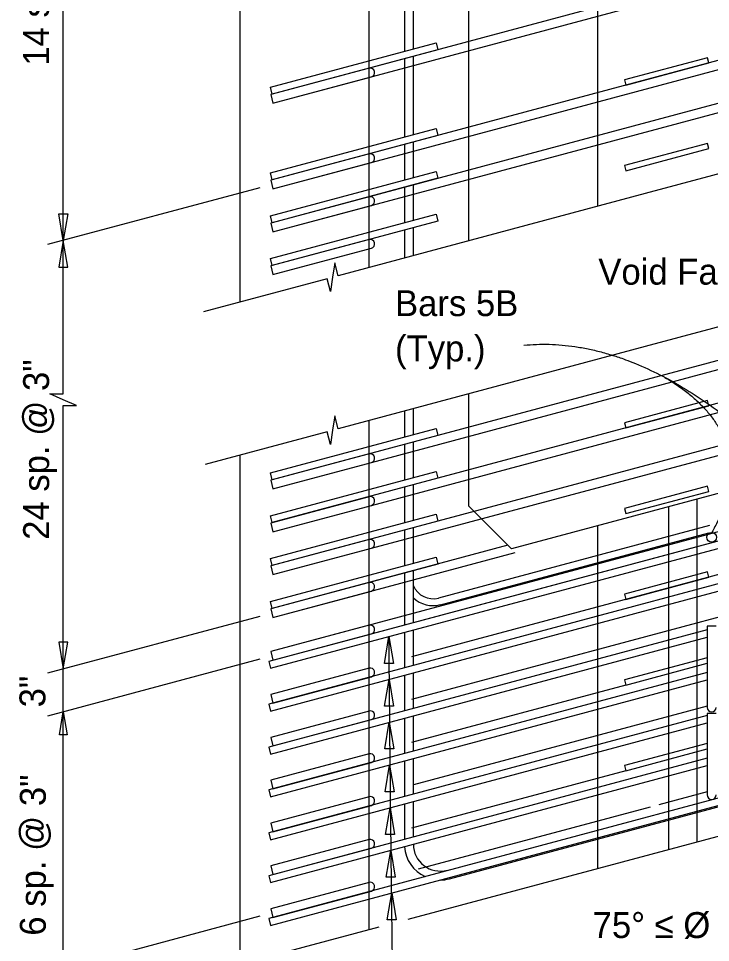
# Model space of a CAD drawing. Extents: x 120658.6 to 120712.1, y 120647.1 to 120669.9.
# Drawn here: x 120676.96 to 120681, y 120653.49 to 120658.88 of the extents above; entities that cross this region are included whole.
import ezdxf

# ---------------------------------------------------------------- set-up
doc = ezdxf.new("R2010")
doc.units = 0
for name, color, linetype in [('BeamConc', 7, 'Continuous'), ('BeamConc_h', 7, 'Continuous'), ('Dimension', 7, 'Continuous'), ('Miscellaneous', 7, 'Continuous'), ('Rebar', 7, 'Continuous'), ('Rebar_h', 7, 'Continuous'), ('TextStructures', 7, 'Continuous')]:
    doc.layers.add(name, color=color, linetype=linetype)

msp = doc.modelspace()

# ---------------------------------------------------------------- linework, layer by layer
at = {"layer": 'BeamConc'}
for p, q in [((120679.5908, 120657.5812), (120679.5908, 120659.5478)), ((120678.2575, 120657.224), (120678.2575, 120659.1906)), ((120684.1025, 120656.9257), (120679.8408, 120655.7838)), ((120679.5908, 120656.0338), (120679.5908, 120656.6888)), ((120678.2575, 120653.4221), (120678.2575, 120656.3316)), ((120679.8408, 120655.7838), (120679.5908, 120656.0338)), ((120687.0305, 120655.7103), (120679.2355, 120653.6216)), ((120679.0655, 120653.5761), (120678.3179, 120653.3758))]:
    msp.add_line(p, q, dxfattribs=at)
at = {"layer": 'BeamConc_h'}
for p, q in [((120680.3408, 120659.7487), (120680.3408, 120657.7821)), ((120679.0075, 120659.3915), (120679.0075, 120657.4249)), ((120679.0075, 120656.5326), (120679.0075, 120653.5605)), ((120680.3408, 120655.9178), (120680.3408, 120653.9178))]:
    msp.add_line(p, q, dxfattribs=at)
at = {"layer": 'Dimension'}
for p, q in [((120678.372, 120657.8903), (120677.1344, 120657.5586)), ((120678.372, 120655.3903), (120677.1344, 120655.0586)), ((120678.372, 120655.1403), (120677.1344, 120654.8086)), ((120678.372, 120653.6403), (120677.1344, 120653.3086))]:
    msp.add_line(p, q, dxfattribs=at)
for points in [[(120677.226, 120657.5832), (120677.226, 120659.3202), (120677.3035, 120659.3202), (120677.226, 120659.354), (120677.1485, 120659.3877), (120677.226, 120659.3877), (120677.226, 120666.7254)], [(120684.7814, 120658.9716), (120682.7067, 120658.4158), (120682.6867, 120658.4906), (120682.6742, 120658.4071), (120682.6615, 120658.3234), (120682.6415, 120658.3983), (120680.6202, 120657.8569)], [(120685.0801, 120658.1592), (120682.7067, 120657.5235), (120682.6867, 120657.5983), (120682.6742, 120657.5147), (120682.6615, 120657.4311), (120682.6415, 120657.506), (120680.6202, 120656.9646)], [(120680.6202, 120657.8569), (120678.8294, 120657.3772), (120678.8094, 120657.452), (120678.7969, 120657.3685), (120678.7842, 120657.2848), (120678.7642, 120657.3597), (120678.0441, 120657.1668)], [(120677.226, 120652.0096), (120677.226, 120656.6201), (120677.3035, 120656.6201), (120677.226, 120656.6539), (120677.1485, 120656.6876), (120677.226, 120656.6876), (120677.226, 120657.5832)], [(120680.6202, 120656.9646), (120678.8294, 120656.4849), (120678.8094, 120656.5597), (120678.7969, 120656.4761), (120678.7842, 120656.3925), (120678.7642, 120656.4674), (120678.0531, 120656.2769)]]:
    msp.add_lwpolyline(points, dxfattribs=at)
for points in [[(120677.226, 120657.5832), (120677.1996, 120657.7394), (120677.2525, 120657.7394)], [(120677.226, 120657.5832), (120677.1996, 120657.427), (120677.2525, 120657.427)], [(120679.1251, 120655.2719), (120679.1516, 120655.1157), (120679.0986, 120655.1157)], [(120677.226, 120655.0832), (120677.2525, 120655.2394), (120677.1996, 120655.2394)], [(120679.126, 120655.0222), (120679.1525, 120654.866), (120679.0996, 120654.866)], [(120677.2261, 120654.8331), (120677.2482, 120654.6993), (120677.204, 120654.6993)], [(120679.1273, 120654.7726), (120679.1538, 120654.6164), (120679.1008, 120654.6164)], [(120679.1293, 120654.523), (120679.1557, 120654.3668), (120679.1028, 120654.3668)], [(120679.132, 120654.2738), (120679.1584, 120654.1176), (120679.1055, 120654.1176)], [(120679.1358, 120654.0248), (120679.1623, 120653.8686), (120679.1094, 120653.8686)], [(120679.1419, 120653.7765), (120679.1683, 120653.6203), (120679.1154, 120653.6203)]]:
    msp.add_lwpolyline(points, close=True, dxfattribs=at)
for points in [[(120679.9122, 120656.9718), (120680.71, 120657.051), (120681.6484, 120656.0418)], [(120680.7352, 120656.7842), (120681.3153, 120656.4395), (120681.0094, 120655.88)], [(120679.5373, 120652.9108), (120679.2444, 120652.879), (120679.1509, 120653.1895), (120679.1427, 120653.5375), (120679.1252, 120655.2719)]]:
    msp.add_open_spline(points, degree=2, dxfattribs=at)
at = {"layer": 'Miscellaneous'}
for p, q in [((120680.922, 120656.0735), (120680.922, 120654.0735)), ((120680.7553, 120656.0289), (120680.7553, 120654.0289))]:
    msp.add_line(p, q, dxfattribs=at)
at = {"layer": 'Rebar'}
for p, q in [((120679.2158, 120659.1433), (120679.2158, 120658.6865)), ((120679.2679, 120658.7005), (120679.2679, 120659.1573)), ((120678.4342, 120658.4771), (120679.4002, 120658.7359)), ((120679.4109, 120658.6956), (120678.445, 120658.4368)), ((120679.4002, 120658.7359), (120679.4109, 120658.6956)), ((120679.2158, 120658.6433), (120679.2158, 120658.1865)), ((120679.2679, 120658.2005), (120679.2679, 120658.6573)), ((120679.0093, 120658.5879), (120678.4356, 120658.4342)), ((120678.449, 120658.3839), (120679.0228, 120658.5376)), ((120678.445, 120658.4368), (120678.4342, 120658.4771)), ((120678.4356, 120658.4342), (120678.449, 120658.3839)), ((120678.4342, 120657.9771), (120679.4002, 120658.2359)), ((120679.4002, 120658.2359), (120679.4109, 120658.1956)), ((120679.4109, 120658.1956), (120678.445, 120657.9368)), ((120679.2679, 120657.9505), (120679.2679, 120658.1573)), ((120679.2158, 120658.1433), (120679.2158, 120657.9365)), ((120679.0093, 120658.0879), (120678.4356, 120657.9342)), ((120678.449, 120657.8839), (120679.0228, 120658.0376)), ((120678.4342, 120657.7271), (120679.4002, 120657.9859)), ((120678.445, 120657.9368), (120678.4342, 120657.9771)), ((120679.4109, 120657.9456), (120678.445, 120657.6868)), ((120679.4002, 120657.9859), (120679.4109, 120657.9456)), ((120678.4356, 120657.9342), (120678.449, 120657.8839)), ((120679.2158, 120657.8933), (120679.2158, 120657.6865)), ((120679.2679, 120657.7005), (120679.2679, 120657.9073)), ((120679.0093, 120657.8379), (120678.4356, 120657.6842)), ((120678.449, 120657.6339), (120679.0228, 120657.7876)), ((120678.4342, 120657.4771), (120679.4002, 120657.7359)), ((120678.445, 120657.6868), (120678.4342, 120657.7271)), ((120679.4002, 120657.7359), (120679.4109, 120657.6956)), ((120678.4356, 120657.6842), (120678.449, 120657.6339)), ((120679.4109, 120657.6956), (120678.445, 120657.4368)), ((120679.2158, 120657.6433), (120679.2158, 120657.4807)), ((120679.2679, 120657.4947), (120679.2679, 120657.6573)), ((120679.0093, 120657.5879), (120678.4356, 120657.4342)), ((120678.449, 120657.3839), (120679.0228, 120657.5376)), ((120678.445, 120657.4368), (120678.4342, 120657.4771)), ((120678.4356, 120657.4342), (120678.449, 120657.3839)), ((120686.9134, 120657.1519), (120678.4242, 120654.8772)), ((120678.435, 120654.837), (120686.9242, 120657.1117)), ((120685.4351, 120657.0058), (120678.4242, 120655.1272)), ((120678.435, 120655.087), (120685.4459, 120656.9656)), ((120679.2679, 120656.4505), (120679.2679, 120656.6023)), ((120679.2158, 120656.5884), (120679.2158, 120656.4365)), ((120678.4342, 120656.2271), (120679.4002, 120656.4859)), ((120679.4002, 120656.4859), (120679.4109, 120656.4456)), ((120679.4109, 120656.4456), (120678.445, 120656.1868)), ((120679.2158, 120656.3933), (120679.2158, 120656.1865)), ((120679.2679, 120656.2005), (120679.2679, 120656.4073)), ((120679.0093, 120656.3379), (120678.4356, 120656.1842)), ((120678.449, 120656.1339), (120679.0228, 120656.2876)), ((120678.4342, 120655.9771), (120679.4002, 120656.2359)), ((120678.445, 120656.1868), (120678.4342, 120656.2271)), ((120679.4002, 120656.2359), (120679.4109, 120656.1956)), ((120678.4356, 120656.1842), (120678.449, 120656.1339)), ((120679.4109, 120656.1956), (120678.445, 120655.9368)), ((120679.2158, 120656.1433), (120679.2158, 120655.9365)), ((120679.2679, 120655.9505), (120679.2679, 120656.1573)), ((120679.0093, 120656.0879), (120678.4356, 120655.9342)), ((120678.449, 120655.8839), (120679.0228, 120656.0376)), ((120678.4342, 120655.7271), (120679.4002, 120655.9859)), ((120678.445, 120655.9368), (120678.4342, 120655.9771)), ((120679.4109, 120655.9456), (120678.445, 120655.6868)), ((120679.4002, 120655.9859), (120679.4109, 120655.9456)), ((120678.4356, 120655.9342), (120678.449, 120655.8839)), ((120679.2158, 120655.8933), (120679.2158, 120655.6865)), ((120679.2679, 120655.7005), (120679.2679, 120655.9073)), ((120680.9942, 120655.9203), (120679.4149, 120655.4971)), ((120679.0093, 120655.8379), (120678.4356, 120655.6842)), ((120679.4257, 120655.4583), (120680.992, 120655.8781)), ((120678.449, 120655.6339), (120679.0228, 120655.7876)), ((120678.4342, 120655.4771), (120679.4002, 120655.7359)), ((120679.4002, 120655.7359), (120679.4109, 120655.6956)), ((120678.445, 120655.6868), (120678.4342, 120655.7271)), ((120678.4356, 120655.6842), (120678.449, 120655.6339)), ((120679.4109, 120655.6956), (120678.445, 120655.4368)), ((120679.2158, 120655.6433), (120679.2158, 120655.3394)), ((120679.2679, 120655.3533), (120679.2679, 120655.6573)), ((120685.7448, 120655.5888), (120678.4242, 120653.6272)), ((120679.0093, 120655.5879), (120678.4356, 120655.4342)), ((120679.4781, 120653.8592), (120685.9781, 120655.6009)), ((120678.435, 120653.587), (120685.7573, 120655.549)), ((120678.449, 120655.3839), (120679.0228, 120655.5376)), ((120678.445, 120655.4368), (120678.4342, 120655.4771)), ((120678.4356, 120655.4342), (120678.449, 120655.3839)), ((120680.9815, 120655.3125), (120678.4242, 120654.6272)), ((120679.0093, 120655.3379), (120678.4356, 120655.1842)), ((120679.2679, 120655.1033), (120679.2679, 120655.3102)), ((120680.9815, 120655.3325), (120680.9815, 120654.8585)), ((120681.0335, 120655.3325), (120680.9815, 120655.3325)), ((120678.435, 120654.587), (120680.9815, 120655.2693)), ((120678.449, 120655.1339), (120679.0228, 120655.2876)), ((120679.2158, 120655.2962), (120679.2158, 120655.0894)), ((120678.4356, 120655.1842), (120678.449, 120655.1339)), ((120678.4242, 120655.1272), (120678.435, 120655.087)), ((120679.0093, 120655.0879), (120678.4356, 120654.9342)), ((120680.9815, 120655.0625), (120678.4242, 120654.3772)), ((120678.449, 120654.8839), (120679.0228, 120655.0376)), ((120679.2158, 120655.0462), (120679.2158, 120654.8394)), ((120679.2679, 120654.8533), (120679.2679, 120655.0602)), ((120678.435, 120654.337), (120680.9815, 120655.0193)), ((120678.4356, 120654.9342), (120678.449, 120654.8839)), ((120678.4242, 120654.8772), (120678.435, 120654.837)), ((120679.0093, 120654.8379), (120678.4356, 120654.6842)), ((120680.9815, 120654.8225), (120680.9815, 120654.3485)), ((120681.0335, 120654.8225), (120680.9815, 120654.8225)), ((120680.9815, 120654.8125), (120678.4242, 120654.1272)), ((120678.435, 120654.087), (120680.9815, 120654.7693)), ((120678.449, 120654.6339), (120679.0228, 120654.7876)), ((120679.2158, 120654.7962), (120679.2158, 120654.5894)), ((120679.2679, 120654.6033), (120679.2679, 120654.8102)), ((120678.4356, 120654.6842), (120678.449, 120654.6339)), ((120678.4242, 120654.6272), (120678.435, 120654.587)), ((120680.9815, 120654.5625), (120678.4242, 120653.8772)), ((120679.0093, 120654.5879), (120678.4356, 120654.4342)), ((120679.2158, 120654.5462), (120679.2158, 120654.3394)), ((120679.2679, 120654.3534), (120679.2679, 120654.5602)), ((120678.435, 120653.837), (120680.9815, 120654.5193)), ((120678.449, 120654.3839), (120679.0228, 120654.5376)), ((120678.4356, 120654.4342), (120678.449, 120654.3839)), ((120678.4242, 120654.3772), (120678.435, 120654.337)), ((120679.0093, 120654.3379), (120678.4356, 120654.1842)), ((120678.449, 120654.1339), (120679.0228, 120654.2876)), ((120679.2158, 120654.2962), (120679.2158, 120654.0894)), ((120679.2679, 120654.1033), (120679.2679, 120654.3102)), ((120678.4356, 120654.1842), (120678.449, 120654.1339)), ((120678.4242, 120654.1272), (120678.435, 120654.087)), ((120679.0093, 120654.0879), (120678.4356, 120653.9342)), ((120678.449, 120653.8839), (120679.0228, 120654.0376)), ((120678.4356, 120653.9342), (120678.449, 120653.8839)), ((120678.4242, 120653.8772), (120678.435, 120653.837)), ((120679.0093, 120653.8379), (120678.4356, 120653.6842)), ((120678.449, 120653.6339), (120679.0228, 120653.7876)), ((120678.4356, 120653.6842), (120678.449, 120653.6339)), ((120678.4242, 120653.6272), (120678.435, 120653.587))]:
    msp.add_line(p, q, dxfattribs=at)
for points in [[(120680.5075, 120658.4894), (120680.9905, 120658.6188), (120680.9824, 120658.649), (120680.4994, 120658.5196)], [(120680.5075, 120657.9894), (120680.9905, 120658.1188), (120680.9824, 120658.149), (120680.4994, 120658.0196)], [(120680.5075, 120656.4894), (120680.9905, 120656.6188), (120680.9824, 120656.649), (120680.4994, 120656.5196)], [(120680.5075, 120655.9894), (120680.9905, 120656.1188), (120680.9824, 120656.149), (120680.4994, 120656.0196)], [(120680.5075, 120655.4894), (120680.9905, 120655.6188), (120680.9824, 120655.649), (120680.4994, 120655.5196)]]:
    msp.add_lwpolyline(points, close=True, dxfattribs=at)
for points in [[(120680.9815, 120655.1487), (120680.4994, 120655.0196), (120680.5075, 120654.9894), (120680.9815, 120655.1164)], [(120680.9815, 120654.6487), (120680.4994, 120654.5196), (120680.5075, 120654.4894), (120680.9815, 120654.6164)]]:
    msp.add_lwpolyline(points, dxfattribs=at)
msp.add_circle((120681.0075, 120655.8514), 0.0287, dxfattribs=at)
for centre, radius, start, end in [((120679.016, 120658.5628), 0.026, 285, 105), ((120679.016, 120658.0628), 0.026, 285, 105), ((120679.016, 120657.8128), 0.026, 285, 105), ((120679.016, 120657.5628), 0.026, 285, 105), ((120679.016, 120656.3128), 0.026, 285, 105), ((120679.016, 120656.0628), 0.026, 285, 105), ((120679.016, 120655.8128), 0.026, 285, 105), ((120679.016, 120655.5628), 0.026, 285, 105), ((120679.3825, 120655.6179), 0.125, 203.5565, 285), ((120679.3825, 120655.6194), 0.1667, 226.5625, 285), ((120679.016, 120655.3128), 0.026, 285, 105), ((120679.016, 120655.0628), 0.026, 285, 105), ((120679.016, 120654.8128), 0.026, 285, 105), ((120681.0075, 120654.8585), 0.026, 179.9998, 359.9995), ((120679.016, 120654.5628), 0.026, 285, 105), ((120679.016, 120654.3128), 0.026, 285, 105), ((120681.0075, 120654.3485), 0.026, 179.9998, 359.9995), ((120679.016, 120654.0628), 0.026, 285, 105), ((120679.4241, 120654.0604), 0.1562, 180, 285), ((120679.4241, 120654.0604), 0.2083, 183.8665, 245.0097), ((120679.4241, 120654.0604), 0.2083, 270.0611, 285), ((120679.016, 120653.8128), 0.026, 285, 105)]:
    msp.add_arc(centre, radius, start, end, dxfattribs=at)
at = {"layer": 'Rebar_h'}
for p, q in [((120685.1478, 120657.9828), (120679.411, 120656.4456)), ((120679.0228, 120656.2877), (120685.1613, 120657.9325)), ((120685.2103, 120657.7495), (120679.411, 120656.1956)), ((120679.0228, 120656.0377), (120685.2238, 120657.6993)), ((120685.2728, 120657.5163), (120679.411, 120655.9456)), ((120679.0228, 120655.7877), (120685.2863, 120657.466)), ((120685.4216, 120657.0561), (120678.4356, 120655.1842)), ((120678.4356, 120655.9342), (120678.449, 120655.884)), ((120679.8196, 120655.8051), (120678.4356, 120655.4342)), ((120678.449, 120655.134), (120680.9815, 120655.8125)), ((120678.449, 120655.384), (120679.8621, 120655.7626)), ((120678.4356, 120655.6842), (120678.449, 120655.634)), ((120678.4356, 120655.4342), (120678.449, 120655.384)), ((120678.4356, 120655.1842), (120678.449, 120655.134)), ((120680.9815, 120654.3664), (120680.7002, 120654.291)), ((120680.6481, 120654.2771), (120679.2957, 120653.9147)), ((120678.4356, 120653.6842), (120678.449, 120653.634))]:
    msp.add_line(p, q, dxfattribs=at)
for points in [[(120686.8895, 120660.6994), (120678.4356, 120658.4342), (120678.449, 120658.384), (120686.9029, 120660.6492)], [(120686.8895, 120660.1994), (120678.4356, 120657.9342), (120678.449, 120657.884), (120686.9029, 120660.1492)], [(120686.8895, 120659.9494), (120678.4356, 120657.6842), (120678.449, 120657.634), (120686.9029, 120659.8992)]]:
    msp.add_lwpolyline(points, close=True, dxfattribs=at)
for points in [[(120686.0908, 120656.9854), (120679.2575, 120655.1545)], [(120686.0804, 120656.7327), (120679.2575, 120654.9045)], [(120680.5075, 120654.9894), (120679.2575, 120654.6545)], [(120680.9815, 120654.8664), (120679.2679, 120654.4073)], [(120680.5075, 120654.4894), (120679.2575, 120654.1545)]]:
    msp.add_lwpolyline(points, dxfattribs=at)

# ---------------------------------------------------------------- texts
at = {"layer": 'Dimension'}
for s, p in [('Bars 5B', (120679.1608, 120657.1417)), ('(Typ.)', (120679.1608, 120656.8777))]:
    msp.add_text(s, height=0.1512, dxfattribs=at).set_placement(p)
at = {"layer": 'TextStructures'}
for s, p in [('14 sp. @ 6" ', (120677.1431, 120658.6026)), ('24 sp. @ 3"', (120677.1431, 120655.8366)), ('3"', (120677.1217, 120654.8593)), ('6 sp. @ 3"', (120677.124, 120653.5272))]:
    msp.add_text(s, height=0.1512, rotation=90, dxfattribs=at).set_placement(p)
for s, p in [('Void Face', (120680.3464, 120657.3254)), ('75° ≤ Ø ≤ 90°', (120680.3133, 120653.5136))]:
    msp.add_text(s, height=0.1512, dxfattribs=at).set_placement(p)

doc.saveas('drawing.dxf')
